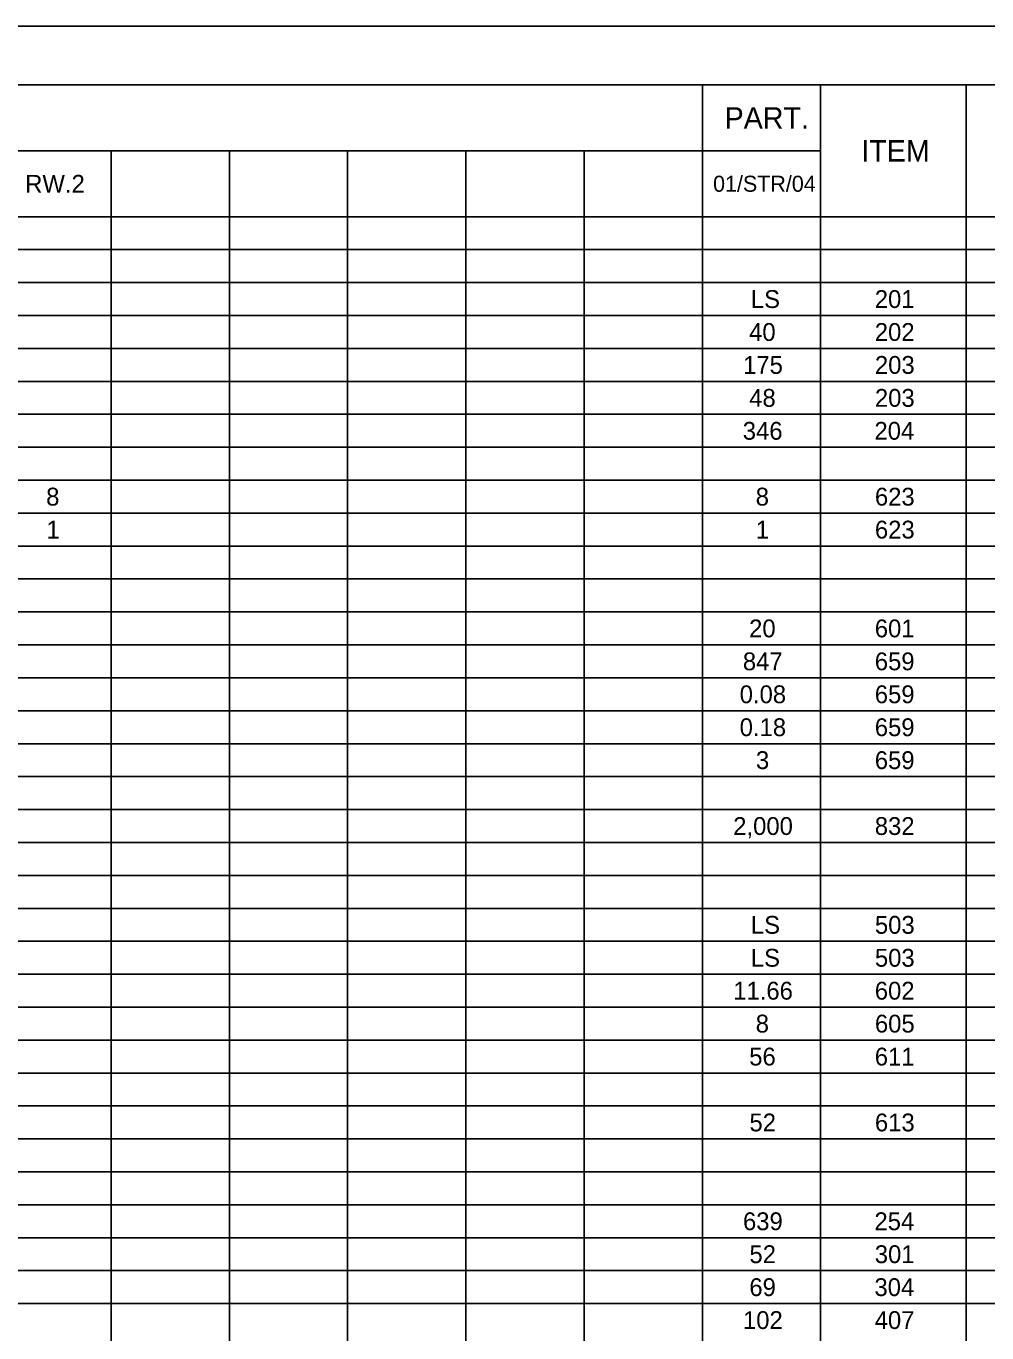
# Model space of a CAD drawing. Extents: x 0 to 34, y 0 to 22.
# Drawn here: x 8.82 to 16.98, y 10.89 to 22 of the extents above; entities that cross this region are included whole.
import ezdxf

# ---------------------------------------------------------------- set-up
doc = ezdxf.new("R2010")
doc.units = 0
for name, color, linetype in [('SH_Border', 7, 'Continuous'), ('SH_Cut_Line', 7, 'Continuous'), ('SH_Text', 7, 'Continuous')]:
    doc.layers.add(name, color=color, linetype=linetype)

msp = doc.modelspace()

# ---------------------------------------------------------------- linework, layer by layer
at = {"layer": 'SH_Border'}
msp.add_lwpolyline([(1.5, 21.5), (33.5, 21.5), (33.5, 0.5), (1.5, 0.5)], close=True, dxfattribs=at)
at = {"layer": 'SH_Cut_Line'}
msp.add_lwpolyline([(0, 0), (34, 0), (34, 22), (0, 22)], close=True, dxfattribs=at)
at = {"layer": 'SH_Text'}
for p, q in [((1.5, 21.5), (32.004, 21.5)), ((14.561, 21.5), (14.561, 0.5)), ((15.566, 21.5), (15.566, 0.5)), ((16.801, 21.5), (16.801, 0.5)), ((1.5, 20.94), (15.566, 20.94)), ((9.538, 20.94), (9.538, 0.5)), ((10.542, 20.94), (10.542, 0.5)), ((11.547, 20.94), (11.547, 0.5)), ((12.552, 20.94), (12.552, 0.5)), ((13.556, 20.94), (13.556, 0.5)), ((1.5, 20.38), (32.004, 20.38)), ((1.5, 20.1), (32.004, 20.1)), ((1.5, 19.82), (32.004, 19.82)), ((1.5, 19.54), (32.004, 19.54)), ((1.5, 19.26), (32.004, 19.26)), ((1.5, 18.98), (32.004, 18.98)), ((1.5, 18.7), (32.004, 18.7)), ((1.5, 18.42), (32.004, 18.42)), ((1.5, 18.14), (32.004, 18.14)), ((1.5, 17.86), (32.004, 17.86)), ((1.5, 17.58), (32.004, 17.58)), ((1.5, 17.3), (32.004, 17.3)), ((1.5, 17.02), (32.004, 17.02)), ((1.5, 16.74), (32.004, 16.74)), ((1.5, 16.46), (32.004, 16.46)), ((1.5, 16.18), (32.004, 16.18)), ((1.5, 15.9), (32.004, 15.9)), ((1.5, 15.62), (32.004, 15.62)), ((1.5, 15.34), (32.004, 15.34)), ((1.5, 15.06), (32.004, 15.06)), ((1.5, 14.78), (32.004, 14.78)), ((1.5, 14.5), (32.004, 14.5)), ((1.5, 14.22), (32.004, 14.22)), ((1.5, 13.94), (32.004, 13.94)), ((1.5, 13.66), (32.004, 13.66)), ((1.5, 13.38), (32.004, 13.38)), ((1.5, 13.1), (32.004, 13.1)), ((1.5, 12.82), (32.004, 12.82)), ((1.5, 12.54), (32.004, 12.54)), ((1.5, 12.26), (32.004, 12.26)), ((1.5, 11.98), (32.004, 11.98)), ((1.5, 11.7), (32.004, 11.7)), ((1.5, 11.42), (32.004, 11.42)), ((1.5, 11.14), (32.004, 11.14))]:
    msp.add_line(p, q, dxfattribs=at)

# ---------------------------------------------------------------- texts
for s, height, p in [('PART.', 0.1818, (14.75, 21.129)), ('ITEM', 0.1818, (15.912, 20.849)), ('RW.2', 0.1515, (8.807, 20.584)), ('01/STR/04', 0.1364, (14.652, 20.592)), ('LS', 0.1515, (14.973, 19.604)), ('201', 0.1515, (16.026, 19.604)), ('40', 0.1515, (14.958, 19.324)), ('202', 0.1515, (16.026, 19.324)), ('175', 0.1515, (14.907, 19.044)), ('203', 0.1515, (16.027, 19.044)), ('48', 0.1515, (14.959, 18.764)), ('203', 0.1515, (16.027, 18.764)), ('346', 0.1515, (14.904, 18.484)), ('204', 0.1515, (16.023, 18.484)), ('8', 0.152, (8.985, 17.924)), ('8', 0.152, (15.014, 17.924)), ('623', 0.1515, (16.027, 17.924)), ('1', 0.152, (8.987, 17.644)), ('1', 0.152, (15.015, 17.644)), ('623', 0.1515, (16.027, 17.644)), ('20', 0.1515, (14.958, 16.804)), ('601', 0.1515, (16.026, 16.804)), ('847', 0.1515, (14.905, 16.524)), ('659', 0.1515, (16.026, 16.524)), ('0.08', 0.1515, (14.878, 16.244)), ('659', 0.1515, (16.026, 16.244)), ('0.18', 0.1515, (14.878, 15.964)), ('659', 0.1515, (16.026, 15.964)), ('3', 0.152, (15.016, 15.684)), ('659', 0.1515, (16.026, 15.684)), ('2,000', 0.1515, (14.823, 15.124)), ('832', 0.1515, (16.026, 15.124)), ('LS', 0.1515, (14.973, 14.284)), ('503', 0.1515, (16.027, 14.284)), ('LS', 0.1515, (14.973, 14.004)), ('503', 0.1515, (16.027, 14.004)), ('11.66', 0.1515, (14.823, 13.724)), ('602', 0.1515, (16.026, 13.724)), ('8', 0.152, (15.014, 13.444)), ('605', 0.1515, (16.027, 13.444)), ('56', 0.1515, (14.959, 13.164)), ('611', 0.1515, (16.026, 13.164)), ('52', 0.1515, (14.961, 12.604)), ('613', 0.1515, (16.027, 12.604)), ('639', 0.1515, (14.906, 11.764)), ('254', 0.1515, (16.023, 11.764)), ('52', 0.1515, (14.961, 11.484)), ('301', 0.1515, (16.026, 11.484)), ('69', 0.1515, (14.96, 11.204)), ('304', 0.1515, (16.023, 11.204)), ('102', 0.1515, (14.906, 10.924)), ('407', 0.1515, (16.025, 10.924))]:
    msp.add_text(s, height=height, dxfattribs=at).set_placement(p)

doc.saveas('drawing.dxf')
